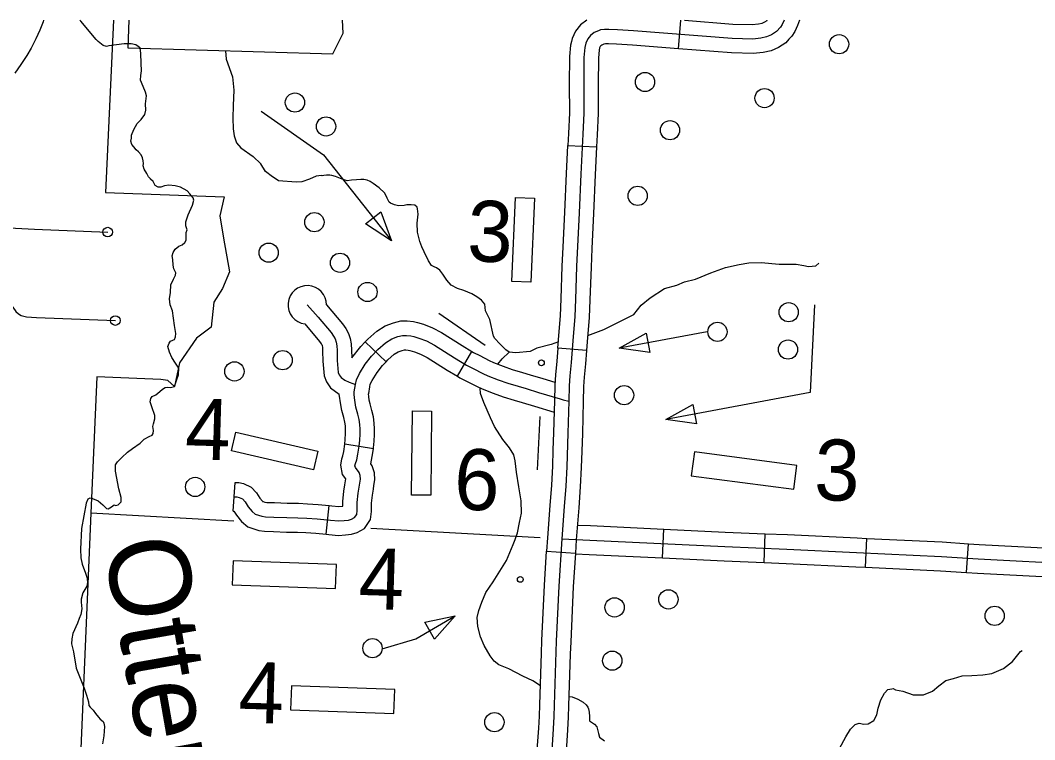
# Model space of a CAD drawing. Extents: x 653372 to 905732, y 627442 to 787275.
# Drawn here: x 690649 to 695924, y 783537 to 787275 of the extents above; entities that cross this region are included whole.
import ezdxf

# ---------------------------------------------------------------- set-up
doc = ezdxf.new("R2010")
doc.units = 0
for name, color, linetype in [('10', 7, 'Continuous'), ('21', 7, 'Continuous'), ('31', 7, 'Continuous'), ('32', 7, 'Continuous'), ('33', 7, 'Continuous'), ('35', 7, 'Continuous'), ('5', 7, 'Continuous'), ('56', 7, 'Continuous'), ('57', 7, 'Continuous'), ('6', 7, 'Continuous')]:
    doc.layers.add(name, color=color, linetype=linetype)

msp = doc.modelspace()

# ---------------------------------------------------------------- linework, layer by layer
at = {"layer": '10'}
msp.add_lwpolyline([(690769.4, 787274.7), (690767.2, 787267.6), (690749.8, 787223.6), (690729.5, 787178.2), (690705, 787129.1), (690682.6, 787091.5), (690651.9, 787044.5), (690619.9, 787000.7)], dxfattribs=at)
at = {"layer": '21'}
for p, q in [((691212.6, 787274.7), (691208.3, 787131.8)), ((692327.7, 787208.2), (692323.3, 787274.7)), ((692273.6, 787099.8), (692327.7, 787208.2)), ((691208.3, 787131.8), (692273.6, 787099.8))]:
    msp.add_line(p, q, dxfattribs=at)
at = {"layer": '31'}
for p, q in [((694071.5, 787126.7), (694082.9, 787274.7)), ((693495.6, 786623.8), (693645.4, 786616.6)), ((693593.6, 785559.6), (693444.1, 785571.5)), ((693385.6, 784516.3), (693535.3, 784506.7)), ((693535.3, 784506.7), (693535.3, 784506.7))]:
    msp.add_line(p, q, dxfattribs=at)
for points in [[(693594.1, 787274.7), (693562.2, 787250.9), (693536.2, 787218.8), (693518.5, 787180.7), (693514.7, 787164.9)], [(694620.9, 787274.7), (694610.5, 787252.2), (694602.1, 787239.2), (694580.5, 787216.1), (694555.4, 787199.8), (694529.5, 787188.3), (694500, 787181.6), (694457.2, 787177.2), (694350.3, 787180.4), (693837.3, 787220)], [(694102.8, 787274.7), (694354.3, 787255.3), (694454.5, 787252.3), (694487.8, 787255.8), (694505.8, 787259.8), (694519.5, 787266), (694532, 787274), (694532.7, 787274.7)], [(694701.4, 787274.7), (694690.8, 787247.3), (694676.4, 787215.9), (694661.4, 787192.8), (694646, 787176.3)], [(693837.3, 787220), (693753.7, 787225.3), (693709.2, 787227.1), (693686.5, 787226.9), (693666.1, 787224.6), (693654.6, 787220.7), (693633.4, 787210.5), (693614.5, 787196.4), (693600.3, 787178.8), (693589.7, 787155.9), (693584.2, 787133.3), (693579.9, 787082.3), (693578.5, 786941.2), (693578.7, 786791.5), (693573.6, 786683.4), (693563.5, 786475.3), (693554.6, 786273.8), (693541.5, 785994.8), (693535.5, 785824.5), (693531.9, 785735.6), (693522.4, 785609.8), (693513.3, 785496.1), (693506.5, 785427.1), (693503.1, 785376.1), (693500.7, 785295.6), (693496.6, 785130), (693490.4, 784954.9), (693485.5, 784854.7), (693477.6, 784747.9), (693464.9, 784580.6), (693449.1, 784335.2), (693435.7, 784048.6), (693424.8, 783715.4), (693423, 783656.7), (693420.2, 783592.4), (693412, 783479.9)], [(694646, 787176.3), (694629.1, 787158.2), (694591.3, 787133.7), (694553.3, 787116.8), (694512.1, 787107.5), (694459.9, 787102.1), (694346.3, 787105.5), (694071.5, 787126.7)], [(693514.7, 787164.9), (693510, 787145.3), (693504.9, 787085.9), (693503.5, 786941.5), (693503.7, 786793.3), (693498.7, 786687), (693495.6, 786623.8)], [(693660.6, 787129.9), (693658.5, 787121.3), (693654.8, 787078.7), (693653.5, 786940.9), (693653.7, 786789.8), (693648.5, 786679.8), (693645.4, 786616.6)], [(694071.5, 787126.7), (693832, 787145.2), (693749.7, 787150.4), (693708.1, 787152.1), (693691, 787151.9), (693682.7, 787151), (693672.6, 787146.1), (693666.9, 787141.9), (693664.4, 787138.8), (693660.8, 787131.1), (693660.6, 787129.9)], [(693471.2, 786096.3), (693479.7, 786277.2), (693488.6, 786478.8), (693495.6, 786623.8)], [(693645.4, 786616.6), (693638.5, 786471.9), (693629.6, 786270.4), (693621.1, 786089.3)], [(693444.1, 785571.5), (693447.6, 785615.7), (693457, 785739.9), (693460.5, 785827.3), (693466.6, 785997.9), (693471.2, 786096.3)], [(693621.1, 786089.3), (693616.5, 785991.7), (693610.4, 785821.6), (693606.7, 785731.2), (693597.2, 785604), (693593.6, 785559.6)], [(693444.1, 785571.5), (693438.6, 785502.7), (693431.7, 785433.3), (693428.1, 785379.7), (693425.7, 785297.7), (693421.7, 785132.2), (693418.4, 785041)], [(693593.6, 785559.6), (693588, 785489.4), (693581.2, 785420.9), (693578, 785372.4), (693575.6, 785293.6), (693571.6, 785127.7), (693568.3, 785035.7)], [(693418.4, 785041), (693415.5, 784958.1), (693410.7, 784859.3), (693402.8, 784753.5), (693390, 784585.9), (693385.6, 784516.3)], [(693568.3, 785035.7), (693565.4, 784951.8), (693560.4, 784850.1), (693552.4, 784742.2), (693539.7, 784575.4), (693535.3, 784506.7)], [(693358.7, 783986.7), (693360.8, 784051.6), (693374.2, 784339.4), (693385.6, 784516.3)], [(693535.3, 784506.7), (693524, 784331.1), (693510.7, 784045.6), (693508.6, 783981.7)], [(693335.8, 783461.2), (693337.2, 783484.8), (693345.3, 783596.8), (693348.1, 783659.5), (693349.8, 783717.8), (693358.7, 783986.7)], [(693508.6, 783981.7), (693499.8, 783713.1), (693498, 783653.9), (693495, 783588), (693486.9, 783475), (693485.5, 783452.3)]]:
    msp.add_lwpolyline(points, dxfattribs=at)
at = {"layer": '32'}
for p, q in [((692550.9, 785500.1), (692442.1, 785603.3)), ((692921.4, 785424.8), (692997.3, 785554.2)), ((692484.9, 785048.4), (692336.7, 785071.8)), ((691755.2, 784724.1), (691765.6, 784873.7)), ((692238.6, 784604.2), (692254.6, 784753.3)), ((693988.6, 784480.8), (693995.9, 784630.6)), ((694516.7, 784457), (694522.7, 784606.9)), ((695043.6, 784432.8), (695050.7, 784582.6)), ((695569.2, 784405.1), (695579.6, 784554.7))]:
    msp.add_line(p, q, dxfattribs=at)
for points in [[(692141, 785796.3), (692197, 785731.5), (692264.4, 785652.3), (692277.2, 785634.1), (692285.6, 785619), (692290.3, 785602.5), (692294.2, 785583.8), (692295.7, 785558.3), (692297.1, 785507.7), (692301.9, 785445.2), (692307.5, 785432.4), (692317.5, 785418), (692335.6, 785404.1), (692358.3, 785393.8), (692377.4, 785387.3), (692392.1, 785383.1)], [(692241, 785795.5), (692323.7, 785698.3), (692340.7, 785674.1), (692355.4, 785648), (692363.2, 785620.5), (692368.8, 785593.7), (692370.6, 785561.5), (692371.8, 785520.1)], [(692442.1, 785603.3), (692455.3, 785617.2), (692502.4, 785659.8), (692546.5, 785686.6), (692589.1, 785703.4), (692628.1, 785712.5), (692661.2, 785712.7), (692692.7, 785709.5), (692714.4, 785703.7), (692745.4, 785695.2), (692792.6, 785676.9), (692839.4, 785652.2), (692946, 785584.3), (692997.3, 785554.2)], [(692127.7, 785697.2), (692205, 785606.3), (692213.6, 785594.1), (692215.9, 785590), (692217.5, 785584.6), (692219.7, 785574), (692220.7, 785555), (692222.2, 785503.8), (692228.1, 785426.9), (692241.6, 785395.8), (692262.5, 785365.7), (692307.1, 785331.4)], [(692371.8, 785520.1), (692419, 785579), (692442.1, 785603.3)], [(692391.2, 784951.7), (692388, 784960), (692391.3, 784971.8), (692398.5, 784990.8), (692404.6, 785021.1), (692411.1, 785061.8), (692413.5, 785092.9), (692415.2, 785124), (692415.2, 785150), (692414.4, 785174.5), (692410.8, 785199.9), (692404.2, 785229), (692394.1, 785265), (692389.7, 785288.9), (692385.9, 785312.7), (692385.1, 785332.8), (692385.3, 785343.8), (692392.1, 785383.1), (692396.9, 785407.4), (692412, 785439.4), (692442.4, 785488.3), (692475.6, 785529.6), (692507.8, 785563.5), (692547.4, 785599.5), (692580, 785619.2), (692611.5, 785631.6), (692636.9, 785637.5), (692657.7, 785637.7), (692679.2, 785635.5), (692694.6, 785631.3), (692721.9, 785623.8), (692761.5, 785608.5), (692801.7, 785587.3), (692906.9, 785520.3), (692969.6, 785483.5), (693003.3, 785466.2), (693054.4, 785440.1), (693079.3, 785428.2), (693133.6, 785407.3), (693183.6, 785389.5), (693237.8, 785373.2), (693279, 785360.8), (693343.7, 785341.6), (693456.2, 785307), (693471.7, 785302.8), (693500.7, 785295.6)], [(692550.9, 785500.1), (692560.2, 785509.8), (692592.5, 785539.1), (692613.4, 785551.8), (692633.9, 785559.8), (692645.7, 785562.6), (692654.2, 785562.6), (692665.6, 785561.5), (692674.9, 785559), (692698.3, 785552.5), (692730.3, 785540.2), (692763.9, 785522.4), (692867.8, 785456.3), (692921.4, 785424.8)], [(692997.3, 785554.2), (693005.8, 785549.2), (693037.5, 785532.9), (693087.6, 785507.4), (693109, 785497.2), (693159.7, 785477.6), (693207, 785460.7), (693259.4, 785445), (693300.5, 785432.7), (693365.4, 785413.4), (693429.1, 785393.8)], [(692484.9, 785048.4), (692485.6, 785053), (692488.3, 785087.9), (692490.1, 785121.9), (692490.2, 785151.1), (692489.3, 785181.1), (692484.6, 785213.5), (692477, 785247.3), (692467.3, 785282), (692463.6, 785301.6), (692460.7, 785320.2), (692460.1, 785333.5), (692460.2, 785336.4), (692465.9, 785369.4), (692468.7, 785383.8), (692478, 785403.5), (692503.7, 785444.8), (692532.1, 785480.2), (692550.9, 785500.1)], [(692921.4, 785424.8), (692933.5, 785417.8), (692969.1, 785399.4), (693021.3, 785372.8), (693049.6, 785359.3), (693107.5, 785337), (693160.2, 785318.2), (693216.3, 785301.3), (693257.6, 785288.9), (693322, 785269.8), (693424.2, 785238.4)], [(692336.5, 785070.5), (692338.6, 785097.8), (692340.2, 785126.1), (692340.2, 785148.9), (692339.6, 785167.9), (692336.9, 785186.2), (692331.5, 785210.7), (692321, 785247.9), (692315.7, 785276.1), (692307.1, 785331.4)], [(692254.6, 784753.3), (692268.1, 784751.9), (692305.7, 784748.7), (692325.5, 784749.8), (692325.5, 784773.6), (692331.1, 784827.3), (692336.5, 784860.6), (692339.5, 784881.6), (692341.4, 784892.7), (692324.9, 784915.4), (692315.7, 784962.5), (692320, 784995.3), (692326.2, 785011.7), (692330.8, 785034.4), (692336.7, 785071.8)], [(692238.6, 784604.2), (692253.8, 784602.6), (692303.6, 784598.4), (692339.5, 784600.4), (692371.1, 784604.5), (692400.5, 784614), (692438.6, 784634.1), (692470.3, 784680.1), (692475.4, 784722.3), (692475.5, 784765.6), (692479.9, 784807.6), (692484.7, 784838), (692487.7, 784858.3), (692492.4, 784886.1), (692491.1, 784924), (692477.9, 784960.2), (692470.8, 784969.9), (692478.5, 785007.8), (692484.9, 785048.4)], [(691760.4, 784798.9), (691775.2, 784797.9), (691787, 784795.7), (691803.3, 784788.1), (691817.1, 784772.9), (691834.1, 784747.5), (691853.5, 784722.6), (691870.2, 784709.1), (691887.2, 784702.7), (691904.8, 784697.4), (691924.3, 784695), (691967.5, 784693.7), (692034.9, 784690.5), (692092.3, 784690), (692137.8, 784687.4), (692191.6, 784684.6), (692260.9, 784677.2), (692304.7, 784673.5), (692332.5, 784675.1), (692354.5, 784678), (692371.3, 784683.4), (692387.3, 784691.8), (692398.1, 784707.5), (692400.4, 784727), (692400.5, 784769.6), (692405.5, 784817.4), (692410.6, 784849.3), (692413.6, 784869.9), (692417.2, 784891.1), (692416.6, 784909.5), (692411.1, 784924.5), (692391.2, 784951.7)], [(691765.6, 784873.7), (691784.5, 784872.4), (691809.8, 784867.8), (691848.7, 784849.7), (691876.4, 784819.2), (691894.9, 784791.5), (691907.3, 784775.6), (691908, 784775), (691911.3, 784773.8), (691920.2, 784771.1), (691929.9, 784769.9), (691970.4, 784768.7), (692037, 784765.5), (692094.8, 784765), (692141.9, 784762.3), (692197.6, 784759.4), (692254.6, 784753.3)], [(691755.2, 784724.1), (691759.7, 784723.8), (691773.3, 784703.5), (691799.6, 784669.7), (691832.4, 784643.2), (691863.1, 784631.6), (691889.4, 784623.7), (691918.6, 784620.2), (691964.6, 784618.8), (692032.7, 784615.6), (692089.9, 784615), (692133.8, 784612.6), (692185.7, 784609.9), (692238.6, 784604.2)], [(693545.5, 784652.1), (693614.5, 784649), (693995.9, 784630.6)], [(693995.9, 784630.6), (694314.9, 784615.2), (694522.7, 784606.9)], [(694522.7, 784606.9), (694638.2, 784602.2), (695001, 784584.9), (695050.7, 784582.6)], [(693464.9, 784580.6), (693611, 784574.1), (694311.6, 784540.2), (694634.9, 784527.3), (694997.5, 784510), (695439, 784489.3), (695630.1, 784476.1), (696159, 784449.5), (696436.3, 784436.9), (696504, 784432.7), (696542.3, 784428.4), (696579.4, 784420.9), (696602.7, 784413.7), (696611.2, 784412.4), (696651.6, 784406.9), (696717.7, 784400.7), (696832.8, 784394), (696944.8, 784388.5), (697097.3, 784382.9), (697420, 784362.9)], [(695050.7, 784582.6), (695443.3, 784564.2), (695579.6, 784554.7)], [(695579.6, 784554.7), (695634.5, 784550.9), (696105.4, 784527.3)], [(693535, 784502.4), (693607.5, 784499.2), (693988.6, 784480.8)], [(693988.6, 784480.8), (694308.3, 784465.3), (694516.7, 784457)], [(694516.7, 784457), (694631.6, 784452.4), (694993.9, 784435.1), (695043.6, 784432.8)], [(695043.6, 784432.8), (695434.6, 784414.4), (695569.2, 784405.1)], [(695569.2, 784405.1), (695625.6, 784401.2), (696097.9, 784377.5)]]:
    msp.add_lwpolyline(points, dxfattribs=at)
msp.add_arc((692141, 785796.3), 100, 359.5321, 262.3455, dxfattribs=at)
at = {"layer": '33'}
for points in [[(690025.1, 786223.4), (690203.4, 786212.1), (690488.1, 786201.9), (690722.1, 786189.9), (691103.1, 786174.1)], [(690184.7, 785935.5), (690300.1, 785927.8), (690394.5, 785922.4), (690431.9, 785920.8), (690453.8, 785917.1), (690483.8, 785908.7), (690515.4, 785894.3), (690537.9, 785877.6), (690565.1, 785852.8), (690582.9, 785829.2), (690599.6, 785803.2), (690609.6, 785784.7), (690625.9, 785761.7), (690639, 785749.8), (690652.8, 785741.4), (690667.6, 785736.9), (690681.6, 785734.5), (690732.8, 785731), (690870.1, 785725.3), (691142.9, 785714.7)]]:
    msp.add_lwpolyline(points, dxfattribs=at)
for centre in [(691103.1, 786174.1), (691142.9, 785714.7)]:
    msp.add_circle(centre, 25, dxfattribs=at)
at = {"layer": '35'}
for points in [[(691042.9, 787175.8), (690963.6, 787269.6), (690958.5, 787274.7)], [(691263.1, 786590.8), (691250.7, 786600.9), (691238.5, 786616.8), (691228.2, 786629.8), (691223.9, 786647.4), (691226.3, 786662), (691227.7, 786677.5), (691239.3, 786706.7), (691256.8, 786738.3), (691276.9, 786760.1), (691296.2, 786784.9), (691300.7, 786807.1), (691299.8, 786840.3), (691304.9, 786883), (691299.7, 786901.6), (691286.9, 786930.3), (691273.3, 786963.8), (691276, 786988.1), (691279.6, 787012.3), (691276.9, 787051.3), (691274.6, 787103), (691271.5, 787132.3), (691262, 787139.4), (691248.6, 787147.6), (691224.4, 787152.3), (691188.4, 787152.4), (691149.3, 787147.7), (691109.4, 787141.3), (691096.7, 787138.7), (691080.2, 787143.1), (691053.4, 787165.2), (691042.9, 787175.8)], [(691715.8, 787116.6), (691719.3, 787072.1), (691752.7, 786981.5), (691758.3, 786911.2), (691755.9, 786831.4), (691754, 786765.6), (691755.2, 786711), (691760, 786674.8), (691773.5, 786637.4), (691796.1, 786611.4), (691858.7, 786566.9)], [(691450.9, 785616), (691456.2, 785630.5), (691457.7, 785648), (691451.2, 785689.1), (691439.8, 785764.9), (691428.1, 785795.5), (691424.2, 785827.7), (691429.1, 785859.7), (691431.3, 785900.6), (691445.8, 785930.3), (691456.1, 785950.5), (691457.5, 785963.1), (691446.4, 785982.9), (691443.1, 786002.5), (691442, 786032.7), (691438.7, 786051.3), (691444.1, 786068.7), (691453.3, 786085), (691472.3, 786101), (691490.1, 786108.2), (691504, 786119.5), (691511.3, 786132.9), (691511.4, 786171.3), (691516.8, 786186.7), (691509.6, 786206.4), (691510.2, 786227.8), (691521, 786264.5), (691544, 786314.5), (691550.6, 786339.6), (691547, 786352.4), (691530.1, 786373.3), (691516, 786388.4), (691481.5, 786407.9), (691453.5, 786414.6), (691421.4, 786417.5), (691398, 786414.3), (691379.3, 786408), (691364.7, 786407.5), (691350.3, 786415.7), (691346.7, 786423.6), (691339.3, 786437.5), (691325, 786449.6), (691325.1, 786451.6), (691314.7, 786461.6), (691307.4, 786479.4), (691292.5, 786501.2), (691287.2, 786518), (691288.5, 786530.6), (691288, 786544.2), (691284.6, 786560.9), (691276.3, 786575.7), (691263.1, 786590.8)], [(691991.5, 786441.2), (691984.2, 786445.8), (691960.4, 786460.8), (691923.9, 786489.1), (691899, 786528.4), (691858.7, 786566.9)], [(693109.4, 785633.9), (693090.7, 785719.4), (693068.4, 785765.1), (693063.4, 785799.6), (693046.3, 785820.3), (693021.9, 785837.6), (692996.3, 785853.8), (692954.2, 785870.4), (692922.5, 785880.9), (692889.9, 785898.4), (692865.8, 785925.2), (692845.4, 785955.4), (692829.5, 785976.1), (692812.1, 785988.4), (692800.4, 785993.5), (692786.4, 786001.1), (692771.7, 786025.2), (692748.8, 786070.9), (692736.6, 786097.3), (692726.2, 786125.5), (692714.6, 786173.2), (692711.9, 786220.7), (692717.4, 786266.7), (692713.5, 786295.9), (692712, 786303.6), (692700.4, 786313.5), (692681, 786316.4), (692659, 786315.3), (692644.1, 786311.6), (692615.6, 786310.1), (692593.9, 786315.5), (692574, 786323.8), (692567.1, 786330.5), (692562.6, 786336.6), (692556.4, 786349.8), (692550.9, 786361.8), (692541.9, 786378), (692514.3, 786404.4), (692484.1, 786426), (692468.5, 786437.7), (692452.1, 786444.1), (692435.6, 786447), (692419, 786447.5), (692396.4, 786445.2), (692371.5, 786444.2), (692349, 786441.3), (692322.5, 786449.2), (692287.5, 786463.9), (692269.2, 786468), (692257.4, 786469.5), (692240.9, 786470), (692227.2, 786468.7), (692218.8, 786466.5), (692215.7, 786467.8), (692186.6, 786465.1), (692151.8, 786449.6), (692112.9, 786436), (692082.6, 786434.5), (691991.5, 786441.2)], [(693599.6, 785636.1), (693683.6, 785668.5), (693839.8, 785745.6), (693877.9, 785794.2), (693924, 785831.9), (693997.8, 785881.8), (694062, 785899.3), (694101.8, 785915.4), (694159.1, 785929.1), (694239.4, 785962.3), (694316.1, 785990.8), (694386.4, 786005.2), (694437.6, 786014.4), (694501, 786016), (694595.5, 786007.2), (694683.2, 786008.2), (694723.2, 785999.9), (694748, 785995.6), (694784.8, 785999.2), (694800.6, 786013.2)], [(691024, 784790), (691053.9, 784778.4), (691078.5, 784757.2), (691096.5, 784738.1), (691106.2, 784736.9), (691123, 784747.1), (691136, 784756.4), (691145.6, 784753.2), (691157.4, 784756.8), (691172.5, 784771.9), (691173.2, 784795.3), (691161.8, 784839.4), (691144.1, 784931.5), (691144.2, 784964.6), (691153.4, 784980.9), (691176.5, 785002.6), (691206.5, 785030.9), (691231.4, 785049.7), (691271.2, 785077.7), (691292.3, 785097.5), (691319, 785111.3), (691333.8, 785118.6), (691338.9, 785128.2), (691340.4, 785143.7), (691338.1, 785164.3), (691341.4, 785178.8), (691349, 785203.2), (691347.6, 785220.8), (691332.4, 785267), (691323.4, 785291.6), (691326.9, 785310), (691335, 785320.5), (691352.7, 785328.7), (691374.7, 785346.6), (691388.7, 785358.8), (691402.6, 785366.2), (691414.3, 785367.8), (691429.8, 785366.4), (691450.6, 785372.7), (691463.2, 785408.2), (691471.7, 785433.3), (691472.8, 785467.3), (691455, 785493.2), (691437.4, 785522.9), (691423.7, 785550.6), (691415.8, 785580.1), (691423.1, 785597.4), (691430.2, 785606.9), (691441.1, 785612.4), (691450.9, 785616)], [(693446.8, 785604.1), (693409.7, 785590.3), (693334.5, 785571.3), (693299.6, 785553.5), (693225.9, 785547.4), (693190.5, 785549.5), (693173.1, 785563), (693142, 785593.6), (693115.6, 785621.6), (693109.4, 785633.9)], [(693132.2, 785488.2), (693153.8, 785516.5), (693190.5, 785549.5)], [(693353.1, 783817.2), (693314.2, 783841.9), (693262.3, 783867.2), (693189.4, 783904.3), (693136.7, 783926), (693113.6, 783943.9), (693092.5, 783972.3), (693061.6, 784025.4), (693041, 784070.5), (693028.4, 784124.6), (693025.1, 784171.5), (693032.7, 784208.6), (693047.9, 784251.3), (693069.3, 784302.3), (693107.6, 784356.8), (693177.3, 784468.5), (693212.3, 784551.8), (693221.3, 784576.4), (693234.9, 784610.7), (693245.4, 784664.8), (693255.7, 784713.4), (693253, 784778.7), (693240.9, 784851.3), (693229, 784927.1), (693221.3, 784985.4), (693215.1, 785016.4), (693192.5, 785052.6), (693158.3, 785096.3), (693114.1, 785163.5), (693094.1, 785208.4), (693059.8, 785289.2), (693041.1, 785335.9), (693039.5, 785364.1)], [(691024, 784790), (691009.5, 784791.4), (691000.6, 784786.8), (690991.2, 784765.7), (690967.4, 784633.3), (690961.3, 784526.2), (690962.9, 784481.8), (690969.8, 784449.1), (690987, 784401.4), (690996.1, 784375.5), (690997, 784372.5), (690998.4, 784352.8), (690993.9, 784334.2), (690973.1, 784299.4), (690965.3, 784267.2), (690964.8, 784250.5), (690967.7, 784216.9), (690962.9, 784187.5), (690955.4, 784166.1), (690945.8, 784141.8), (690922.6, 784089.3), (690915.8, 784060), (690915, 784034.4), (690925.6, 783992.7), (690938.7, 783907.6), (690962.5, 783847.9), (690979.9, 783805), (690993.6, 783768.2), (691003.4, 783733.5), (691004.8, 783714.7), (691011.4, 783705.7), (691026.7, 783690.4), (691039.9, 783673.3), (691055.1, 783654.1), (691064.6, 783643), (691079, 783631.8), (691083.7, 783621.8), (691086.1, 783605), (691082.7, 783556.9), (691075.6, 783515.7)], [(694909.3, 783491), (694942.4, 783552.4), (694965.3, 783591.3), (694990.7, 783616.2), (695011.7, 783623.1), (695034.3, 783616.7), (695057.1, 783619.9), (695086.9, 783636), (695103, 783665.8), (695109.7, 783700.7), (695124.3, 783743.8), (695143.3, 783779.2), (695160, 783797.6), (695180.9, 783800.8), (695187.6, 783802.5), (695199.7, 783796.4), (695237.7, 783788.4), (695292.1, 783769.7), (695345.1, 783770), (695393.1, 783789.4), (695425.1, 783815.9), (695461.9, 783844.2), (695502, 783854.4), (695547, 783869.1), (695596.2, 783870.5), (695654.1, 783874.4), (695700.7, 783880.6), (695762.1, 783906.2), (695807.7, 783942.7), (695850, 783994.5), (695857.7, 784000.4)], [(693501.3, 783761.3), (693518.7, 783759.6), (693548.7, 783747.3), (693575.7, 783732.3), (693590.4, 783717.7), (693599.5, 783706), (693603, 783696.5), (693607.2, 783679.3), (693609.4, 783656.5), (693607.8, 783634.7), (693623.5, 783623.9), (693634.7, 783616.9), (693646.6, 783603.3), (693650, 783589), (693656, 783568.9), (693660.1, 783549.8), (693686.1, 783531)]]:
    msp.add_lwpolyline(points, dxfattribs=at)
at = {"layer": '5'}
for points in [[(691759.8, 784672.6), (691014.7, 784713.5)], [(693352.7, 784585), (692472.2, 784633.4)]]:
    msp.add_lwpolyline(points, dxfattribs=at)
at = {"layer": '56'}
for p, q in [((692443.6, 786216.9), (692523.5, 786280.3)), ((692523.5, 786280.3), (692578.6, 786128.8)), ((692578.6, 786128.8), (692443.6, 786216.9)), ((693762.2, 785571.6), (693903.5, 785649.5)), ((693903.5, 785649.5), (693921.9, 785549.2)), ((693921.9, 785549.2), (693762.2, 785571.6)), ((694004.9, 785200.6), (694146, 785278.8)), ((694146, 785278.8), (694164.7, 785178.5)), ((694164.7, 785178.5), (694004.9, 785200.6)), ((692752.3, 784147.3), (692910.3, 784179.5)), ((692910.3, 784179.5), (692803.2, 784058.9)), ((692803.2, 784058.9), (692752.3, 784147.3))]:
    msp.add_line(p, q, dxfattribs=at)
for points in [[(691900.4, 786803.4), (692224.6, 786575.1), (692578.6, 786128.8)], [(692825.5, 785752.3), (693065.5, 785586.2)], [(694778, 785796.4), (694756.7, 785340.7), (694004.9, 785200.6)], [(694220.5, 785656), (693762.2, 785571.6)], [(693349.8, 785215.7), (693336.9, 784938.9)], [(692531.2, 784009), (692705.4, 784061.3), (692910.3, 784179.5)]]:
    msp.add_lwpolyline(points, dxfattribs=at)
for points in [[(693223, 786354.8), (693323, 786350.5), (693304.3, 785913.4), (693204.4, 785917.7)], [(692687.7, 785244.9), (692787.7, 785243.9), (692783.5, 784806.5), (692683.5, 784807.4)], [(692195.3, 785035.9), (692172.8, 784938.5), (691746.6, 785037.1), (691769.1, 785134.6)]]:
    msp.add_lwpolyline(points, close=True, dxfattribs=at)
for centre, radius in [((694906.4, 787150.4), 50), ((693897.4, 786954.1), 50), ((694519, 786870.5), 50), ((692076.8, 786847.4), 50), ((692238.6, 786723.3), 50), ((694027.3, 786703.6), 50), ((693859.2, 786362.6), 50), ((692177.9, 786225.8), 50), ((691940.2, 786067.3), 50), ((692311.2, 786014.7), 50), ((692454, 785863.1), 50), ((694644.5, 785757.8), 50), ((694273.8, 785656), 50), ((694640.9, 785563.9), 50), ((692013, 785508.8), 50), ((691762, 785450.4), 50), ((693358.2, 785494.9), 15), ((693788.4, 785327), 50), ((691557.9, 784850.2), 50), ((693248.7, 784369.6), 15), ((693739, 784224.2), 50), ((694018.9, 784265.7), 50), ((695715.4, 784180.3), 50), ((692480.1, 784012.1), 50), ((693726.9, 783947.3), 50), ((693114.1, 783627.6), 50)]:
    msp.add_circle(centre, radius, dxfattribs=at)
at = {"layer": '57'}
for p, q in [((694154.3, 785031.9), (694138, 784908)), ((694687.2, 784962), (694154.3, 785031.9)), ((694670.9, 784838.1), (694687.2, 784962)), ((694138, 784908), (694670.9, 784838.1)), ((691755.2, 784465.8), (691750.7, 784340.9)), ((692292.4, 784446.4), (691755.2, 784465.8)), ((692287.9, 784321.5), (692292.4, 784446.4)), ((691750.7, 784340.9), (692287.9, 784321.5)), ((692059, 783816.9), (692054.5, 783692)), ((692596.1, 783797.5), (692059, 783816.9)), ((692591.6, 783672.6), (692596.1, 783797.5)), ((692054.5, 783692), (692591.6, 783672.6))]:
    msp.add_line(p, q, dxfattribs=at)
at = {"layer": '6'}
for points in [[(691132.9, 787274.7), (691091.6, 786379.3)], [(691091.6, 786379.3), (691708.4, 786357.1), (691687, 786258.1), (691704.6, 786143.2), (691737.2, 785968.4), (691699.8, 785881), (691655.6, 785810.5), (691641.3, 785680.3), (691565.5, 785622.7), (691476.9, 785494.9), (691450.6, 785372.7), (691415.3, 785403.1), (691379.3, 785407.9), (691047.4, 785422.1), (691014.7, 784713.5), (690941.2, 782961.2), (691464.6, 782937.9), (691411.6, 782043.7), (692020.6, 782007.6), (691955.6, 780672.3), (693169, 780626.9)]]:
    msp.add_lwpolyline(points, dxfattribs=at)

# ---------------------------------------------------------------- texts
at = {"layer": '35'}
msp.add_text('Otter', height=422.4, rotation=279.9612, dxfattribs=at).set_placement((691079.4, 784557.8))
at = {"layer": '56'}
for s, p in [('3', (692969.7, 786023.3)), ('6', (692901.2, 784733.4))]:
    msp.add_text(s, height=316.8, rotation=358.28, dxfattribs=at).set_placement(p)
at = {"layer": '57'}
for s, p in [('4', (691502.4, 784995.2)), ('3', (694773.9, 784782.9)), ('4', (692405, 784217.4)), ('4', (691780, 783626.4))]:
    msp.add_text(s, height=316.8, rotation=358.28, dxfattribs=at).set_placement(p)

doc.saveas('drawing.dxf')
